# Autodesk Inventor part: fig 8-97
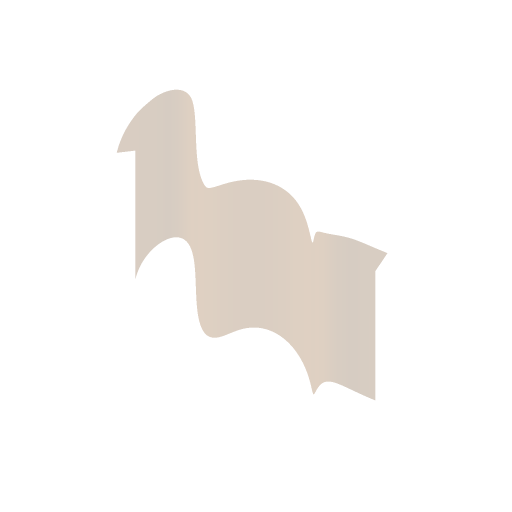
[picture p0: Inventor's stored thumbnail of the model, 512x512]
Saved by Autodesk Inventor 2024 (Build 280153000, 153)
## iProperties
Shininess: 64.0
Length Units: 11269
Angle Units: 11279
Time Units: 11290
Mass Units: 11283
Length Display Precision: 3
Angle Display Precision: 2
Compacted: True
Part Number: fig 8-97
Document SubType Name: Modeling
Created: 2003-08
Designer: Owner
Manufacturer: Standard
Standards Organization: Custom
Density: 1 g/cm^3
Material: Generic
Appearance: Default
Density: 0.0
Volumn: 0.0
Area: 0.0
PropertySet Name: Model Information
Control State: 0
Master: False
Checked Out: False
Author: Owner
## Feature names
1. Split6
## Parameters: d3 = 0, d5 = 0, d6 = 0, d8 = 0
